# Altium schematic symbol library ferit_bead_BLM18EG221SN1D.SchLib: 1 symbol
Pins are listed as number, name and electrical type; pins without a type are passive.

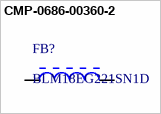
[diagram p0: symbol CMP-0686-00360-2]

## CMP-0686-00360-2
designator FB?, comment BLM18EG221SN1D
Chip Ferrite Bead for GHz Band General Use (Low DC Resistance Type), 220 Ohm, 2000 mA, -55 to 125 degC, 1.6 x 0.8 x 0.95 mm SMD, Tape and Reel; Manufacturer: Murata; Impedance (at 100 MHz): 220 Ohm +/- 25%; Rated Current: 2000 mA; DC Resistance: 0.05 Ohm Max.
footprint MURA-BLM18-RF-H4-CHIP-2_V (Chip Ferrite Bead, 2-Leads, Body 1.6x0.8mm, Height 0.95mm, Reflow)
footprint MURA-BLM18-F-H1-CHIP-2_V (Chip Ferrite Bead, 2-Leads, Body 1.6x0.8mm, Height 0.95mm, Flow)
pins: 1, 2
